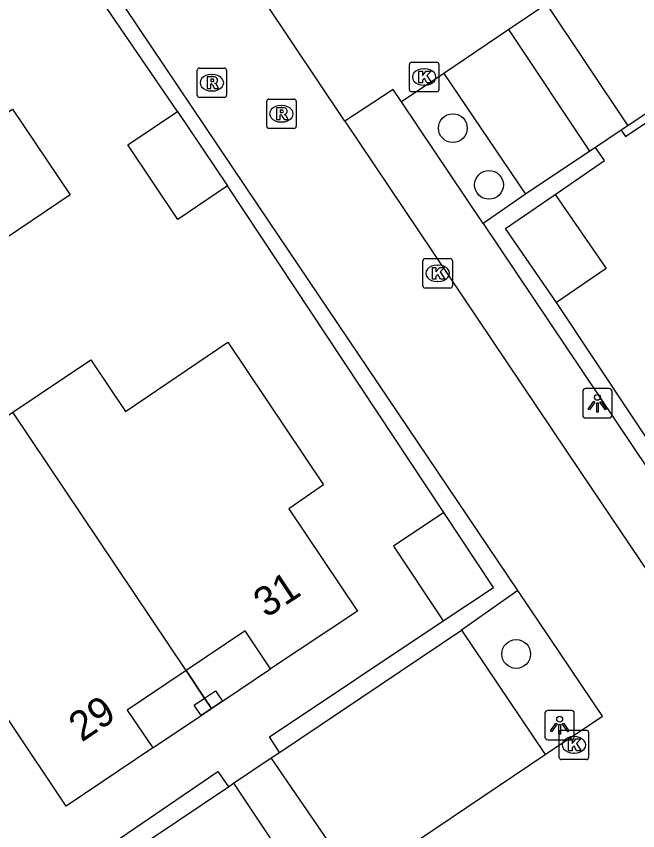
# Model space of a CAD drawing. Extents: x 158797 to 159887, y 384318 to 385255.
# Drawn here: x 158996.31 to 159017.41, y 384665 to 384692.68 of the extents above; entities that cross this region are included whole.
import ezdxf

# ---------------------------------------------------------------- set-up
doc = ezdxf.new("R2010")
doc.units = 0
for name, color, linetype in [('IMGEO_Boom', 7, 'Continuous'), ('IMGEO_Haag', 7, 'Continuous'), ('IMGEO_Kolk', 7, 'Continuous'), ('IMGEO_Lichtpunt', 7, 'Continuous'), ('IMGEO_Pand', 7, 'Continuous'), ('IMGEO_Pand_nummerreeks', 7, 'Continuous'), ('IMGEO_Pand_overbouw', 7, 'Continuous'), ('IMGEO_Parkeervlak_open', 7, 'Continuous'), ('IMGEO_Rijbaan_lokaal_open', 7, 'Continuous'), ('IMGEO_Rioolput', 7, 'Continuous'), ('IMGEO_Voetpad_open', 7, 'Continuous')]:
    doc.layers.add(name, color=color, linetype=linetype)

msp = doc.modelspace()

# ---------------------------------------------------------------- linework, layer by layer
at = {"layer": 'IMGEO_Boom'}
for centre in [(159011.135, 384688.876), (159012.361, 384686.948), (159013.286, 384671.004)]:
    msp.add_circle(centre, 0.489, dxfattribs=at)
at = {"layer": 'IMGEO_Haag'}
for points in [[(159016.845, 384688.805), (159016.999, 384688.587), (159030.87, 384697.932), (159024.718, 384707.573), (159022.492, 384711.051), (159035.359, 384719.573)], [(159001.782, 384689.447), (158999.092, 384693.395), (158999.536, 384693.676)], [(159014.609, 384686.625), (159016.285, 384687.777), (159015.976, 384688.222)], [(159010.822, 384675.811), (159003.482, 384686.92)], [(159013.604, 384686.631), (159012.161, 384685.634)], [(159022.309, 384671.435), (159014.649, 384682.946)], [(159013.342, 384673.159), (159011.423, 384671.817)], [(159005.247, 384667.662), (159004.91, 384668.192), (159010.81, 384672.13)], [(158997.48, 384663.137), (159003.151, 384667.014), (159003.509, 384666.492)]]:
    msp.add_lwpolyline(points, dxfattribs=at)
at = {"layer": 'IMGEO_Kolk'}
for p, q in [((159009.733, 384691.114), (159010.585, 384691.114)), ((159009.658, 384690.188), (159009.658, 384691.04)), ((159010.146, 384690.894), (159010.171, 384690.894)), ((159010.659, 384691.04), (159010.659, 384690.188)), ((159010.169, 384690.334), (159010.144, 384690.334)), ((159010.585, 384690.114), (159009.733, 384690.114)), ((159010.191, 384684.442), (159011.043, 384684.442)), ((159010.116, 384683.516), (159010.116, 384684.368)), ((159010.604, 384684.222), (159010.629, 384684.222)), ((159011.117, 384684.368), (159011.117, 384683.516)), ((159010.627, 384683.662), (159010.602, 384683.662)), ((159011.043, 384683.442), (159010.191, 384683.442)), ((159014.82, 384668.417), (159015.672, 384668.417)), ((159014.745, 384667.491), (159014.745, 384668.343)), ((159015.233, 384668.197), (159015.258, 384668.197)), ((159015.746, 384668.343), (159015.746, 384667.491)), ((159015.256, 384667.637), (159015.231, 384667.637)), ((159015.672, 384667.417), (159014.82, 384667.417))]:
    msp.add_line(p, q, dxfattribs=at)
for points in [[(159009.733, 384691.114), (159010.585, 384691.114)], [(159009.658, 384690.188), (159009.658, 384691.04)], [(159009.979, 384690.814), (159010.102, 384690.814), (159010.102, 384690.663), (159010.232, 384690.814), (159010.396, 384690.814), (159010.25, 384690.663), (159010.403, 384690.414), (159010.251, 384690.414), (159010.166, 384690.578), (159010.102, 384690.511), (159010.102, 384690.414), (159009.979, 384690.414), (159009.979, 384690.814)], [(159010.659, 384691.04), (159010.659, 384690.188)], [(159010.585, 384690.114), (159009.733, 384690.114)], [(159010.191, 384684.442), (159011.043, 384684.442)], [(159010.116, 384683.516), (159010.116, 384684.368)], [(159011.117, 384684.368), (159011.117, 384683.516)], [(159010.437, 384684.142), (159010.56, 384684.142), (159010.56, 384683.991), (159010.69, 384684.142), (159010.854, 384684.142), (159010.708, 384683.991), (159010.861, 384683.742), (159010.709, 384683.742), (159010.624, 384683.906), (159010.56, 384683.839), (159010.56, 384683.742), (159010.437, 384683.742), (159010.437, 384684.142)], [(159011.043, 384683.442), (159010.191, 384683.442)], [(159014.82, 384668.417), (159015.672, 384668.417)], [(159014.745, 384667.491), (159014.745, 384668.343)], [(159015.066, 384668.117), (159015.189, 384668.117), (159015.189, 384667.966), (159015.319, 384668.117), (159015.483, 384668.117), (159015.337, 384667.966), (159015.49, 384667.717), (159015.338, 384667.717), (159015.253, 384667.881), (159015.189, 384667.814), (159015.189, 384667.717), (159015.066, 384667.717), (159015.066, 384668.117)], [(159015.746, 384668.343), (159015.746, 384667.491)], [(159015.672, 384667.417), (159014.82, 384667.417)]]:
    msp.add_lwpolyline(points, dxfattribs=at)
for centre, start, end in [((159009.735, 384691.038), 91.552, 178.448), ((159009.735, 384691.038), 91.552, 178.448), ((159010.583, 384691.038), 1.552, 88.448), ((159010.583, 384691.038), 1.552, 88.448), ((159009.735, 384690.19), 181.552, 268.448), ((159009.735, 384690.19), 181.552, 268.448), ((159010.583, 384690.19), 271.552, 358.448), ((159010.583, 384690.19), 271.552, 358.448), ((159010.193, 384684.366), 91.552, 178.448), ((159010.193, 384684.366), 91.552, 178.448), ((159011.041, 384684.366), 1.552, 88.448), ((159011.041, 384684.366), 1.552, 88.448), ((159010.193, 384683.518), 181.552, 268.448), ((159010.193, 384683.518), 181.552, 268.448), ((159011.041, 384683.518), 271.552, 358.448), ((159011.041, 384683.518), 271.552, 358.448), ((159014.822, 384668.341), 91.552, 178.448), ((159014.822, 384668.341), 91.552, 178.448), ((159015.67, 384668.341), 1.552, 88.448), ((159015.67, 384668.341), 1.552, 88.448), ((159014.822, 384667.493), 181.552, 268.448), ((159014.822, 384667.493), 181.552, 268.448), ((159015.67, 384667.493), 271.552, 358.448), ((159015.67, 384667.493), 271.552, 358.448)]:
    msp.add_arc(centre, 0.0765, start, end, dxfattribs=at)
for centre, major_axis, ratio, start_param, end_param in [((159010.145, 384690.614), (-0.387, 0.002), 0.722429, 4.712389, 7.853982), ((159010.17, 384690.614), (-0.39, 0.002), 0.717154, 1.570796, 4.712389), ((159010.603, 384683.942), (-0.387, 0.002), 0.722429, 4.712389, 7.853982), ((159010.628, 384683.942), (-0.39, 0.002), 0.717154, 1.570796, 4.712389), ((159015.232, 384667.917), (-0.387, 0.002), 0.722429, 4.712389, 7.853982), ((159015.257, 384667.917), (-0.39, 0.002), 0.717154, 1.570796, 4.712389)]:
    msp.add_ellipse(centre, major_axis=major_axis, ratio=ratio, start_param=start_param, end_param=end_param, dxfattribs=at)
at = {"layer": 'IMGEO_Lichtpunt'}
for p, q in [((159016.447, 384680.024), (159015.639, 384680.024)), ((159016.447, 384680.024), (159015.639, 384680.024)), ((159015.545, 384679.929), (159015.545, 384679.122)), ((159015.545, 384679.929), (159015.545, 384679.122)), ((159016.541, 384679.122), (159016.541, 384679.929)), ((159016.541, 384679.122), (159016.541, 384679.929)), ((159015.639, 384679.028), (159016.447, 384679.028)), ((159015.639, 384679.028), (159016.447, 384679.028)), ((159014.263, 384668.991), (159014.263, 384668.184)), ((159014.263, 384668.991), (159014.263, 384668.184)), ((159015.165, 384669.086), (159014.357, 384669.086)), ((159015.165, 384669.086), (159014.357, 384669.086)), ((159015.259, 384668.184), (159015.259, 384668.991)), ((159015.259, 384668.184), (159015.259, 384668.991)), ((159014.357, 384668.09), (159015.165, 384668.09)), ((159014.357, 384668.09), (159015.165, 384668.09))]:
    msp.add_line(p, q, dxfattribs=at)
for points in [[(159015.919, 384679.593), (159015.958, 384679.565), (159015.77, 384679.303), (159015.732, 384679.33), (159015.919, 384679.593)], [(159016.021, 384679.545), (159016.068, 384679.545), (159016.068, 384679.223), (159016.021, 384679.223), (159016.021, 384679.545)], [(159016.131, 384679.565), (159016.169, 384679.592), (159016.356, 384679.33), (159016.317, 384679.302), (159016.131, 384679.565)], [(159014.637, 384668.655), (159014.676, 384668.627), (159014.488, 384668.365), (159014.45, 384668.392), (159014.637, 384668.655)], [(159014.739, 384668.607), (159014.786, 384668.607), (159014.786, 384668.285), (159014.739, 384668.285), (159014.739, 384668.607)], [(159014.849, 384668.627), (159014.887, 384668.654), (159015.074, 384668.392), (159015.035, 384668.364), (159014.849, 384668.627)]]:
    msp.add_lwpolyline(points, dxfattribs=at)
for centre in [(159016.044, 384679.727), (159014.762, 384668.789)]:
    msp.add_circle(centre, 0.0994, dxfattribs=at)
for centre, start, end in [((159015.639, 384679.929), 90, 180), ((159015.639, 384679.929), 90, 180), ((159016.447, 384679.929), 0, 90), ((159016.447, 384679.929), 0, 90), ((159015.639, 384679.122), 180, 270), ((159015.639, 384679.122), 180, 270), ((159016.447, 384679.122), 270, 0), ((159016.447, 384679.122), 270, 360), ((159014.357, 384668.991), 90, 180), ((159014.357, 384668.991), 90, 180), ((159015.165, 384668.991), 0, 90), ((159015.165, 384668.991), 0, 90), ((159014.357, 384668.184), 180, 270), ((159014.357, 384668.184), 180, 270), ((159015.165, 384668.184), 270, 0), ((159015.165, 384668.184), 270, 360)]:
    msp.add_arc(centre, 0.0946, start, end, dxfattribs=at)
at = {"layer": 'IMGEO_Pand'}
for points in [[(158993.552, 384690.663), (158994.895, 384688.659), (158996.173, 384689.52), (158998.134, 384686.609), (158994.667, 384684.273), (158995.465, 384683.072), (158990.615, 384679.83), (158988.303, 384683.292), (158986.558, 384682.126), (158984.781, 384684.772)], [(159003.482, 384686.92), (159001.792, 384685.777), (159000.089, 384688.308), (159001.782, 384689.447)], [(159001.782, 384689.447), (159003.482, 384686.92)], [(159014.649, 384682.946), (159012.919, 384685.463), (159014.609, 384686.625)], [(159014.609, 384686.625), (159016.337, 384684.111), (159014.649, 384682.946)], [(158996.189, 384679.224), (158998.841, 384681.001), (159000.016, 384679.247), (159003.486, 384681.6), (159006.744, 384676.751), (159005.562, 384675.944), (159007.89, 384672.465), (159004.941, 384670.502), (159004.077, 384671.792), (159002.074, 384670.439)], [(159002.074, 384670.439), (159000.077, 384669.091), (159000.945, 384667.812), (158998.004, 384665.834), (158992.405, 384674.193), (158994.691, 384675.724), (158993.536, 384677.447), (158996.189, 384679.224)], [(159002.074, 384670.439), (158996.189, 384679.224)], [(159010.822, 384675.811), (159009.119, 384674.672), (159010.81, 384672.13)], [(159010.81, 384672.13), (159012.516, 384673.264), (159010.822, 384675.811)], [(159002.936, 384669.153), (159002.587, 384668.918), (159002.35, 384669.271), (159002.699, 384669.506)], [(159002.699, 384669.506), (159003.072, 384669.756), (159003.309, 384669.404), (159002.936, 384669.153)], [(159002.936, 384669.153), (159002.699, 384669.506)]]:
    msp.add_lwpolyline(points, dxfattribs=at)
at = {"layer": 'IMGEO_Pand_overbouw'}
for points in [[(159002.074, 384670.439), (159002.699, 384669.506), (159002.936, 384669.153), (159003.309, 384669.404), (159004.941, 384670.502), (159004.077, 384671.792)], [(159002.587, 384668.918), (159002.936, 384669.153), (159002.699, 384669.506), (159002.074, 384670.439), (159000.077, 384669.091), (159000.945, 384667.812)]]:
    msp.add_lwpolyline(points, close=True, dxfattribs=at)
at = {"layer": 'IMGEO_Parkeervlak_open'}
for points in [[(159027.614, 384696.029), (159017.072, 384688.957)], [(159010.828, 384690.734), (159013.604, 384686.631)], [(159015.785, 384688.094), (159013.604, 384686.631)], [(159005.247, 384667.662), (159011.423, 384671.817)], [(159011.423, 384671.817), (159014.269, 384667.587)], [(159004.967, 384667.473), (159005.247, 384667.662)], [(158997.323, 384662.331), (159003.509, 384666.492)], [(159003.509, 384666.492), (159003.688, 384666.613)]]:
    msp.add_lwpolyline(points, dxfattribs=at)
at = {"layer": 'IMGEO_Rijbaan_lokaal_open'}
for points in [[(159013.342, 384673.159), (159004.533, 384686.241), (158999.536, 384693.676)], [(159007.469, 384689.118), (159004.736, 384693.195)], [(159014.319, 384693.094), (159013.039, 384692.228)], [(159013.039, 384692.228), (159010.828, 384690.734)], [(159010.828, 384690.734), (159009.384, 384689.772)], [(159007.469, 384689.118), (159015.48, 384677.168), (159023.424, 384665.376), (159040.186, 384676.652), (159060.67, 384690.454)], [(159009.384, 384689.772), (159009.103, 384690.19), (159007.469, 384689.118)], [(159014.269, 384667.587), (159016.213, 384668.895), (159013.342, 384673.159)], [(159007.845, 384663.262), (159014.269, 384667.587)]]:
    msp.add_lwpolyline(points, dxfattribs=at)
at = {"layer": 'IMGEO_Rioolput'}
for p, q in [((159002.448, 384689.993), (159002.448, 384690.845)), ((159002.523, 384690.919), (159003.375, 384690.919)), ((159003.449, 384690.845), (159003.449, 384689.993)), ((159002.936, 384690.699), (159002.961, 384690.699)), ((159002.959, 384690.139), (159002.934, 384690.139)), ((159003.375, 384689.919), (159002.523, 384689.919)), ((159004.811, 384688.939), (159004.811, 384689.791)), ((159004.886, 384689.865), (159005.738, 384689.865)), ((159005.812, 384689.791), (159005.812, 384688.939)), ((159005.299, 384689.645), (159005.324, 384689.645)), ((159005.738, 384688.865), (159004.886, 384688.865)), ((159005.322, 384689.085), (159005.297, 384689.085))]:
    msp.add_line(p, q, dxfattribs=at)
for points in [[(159002.448, 384689.993), (159002.448, 384690.845)], [(159002.523, 384690.919), (159003.375, 384690.919)], [(159003.449, 384690.845), (159003.449, 384689.993)], [(159003.037, 384690.617), (159002.785, 384690.619), (159002.785, 384690.219)], [(159002.963, 384690.538), (159002.909, 384690.538), (159002.909, 384690.457)], [(159002.785, 384690.219), (159002.909, 384690.219), (159002.909, 384690.381), (159002.92, 384690.381)], [(159002.909, 384690.457), (159002.961, 384690.457)], [(159002.967, 384690.352), (159003.038, 384690.219), (159003.178, 384690.219), (159003.113, 384690.345)], [(159003.375, 384689.919), (159002.523, 384689.919)], [(159004.811, 384688.939), (159004.811, 384689.791)], [(159004.886, 384689.865), (159005.738, 384689.865)], [(159005.812, 384689.791), (159005.812, 384688.939)], [(159005.4, 384689.563), (159005.148, 384689.565), (159005.148, 384689.165)], [(159005.326, 384689.484), (159005.272, 384689.484), (159005.272, 384689.403)], [(159005.148, 384689.165), (159005.272, 384689.165), (159005.272, 384689.327), (159005.283, 384689.327)], [(159005.272, 384689.403), (159005.324, 384689.403)], [(159005.33, 384689.298), (159005.401, 384689.165), (159005.541, 384689.165), (159005.476, 384689.291)], [(159005.738, 384688.865), (159004.886, 384688.865)]]:
    msp.add_lwpolyline(points, dxfattribs=at)
for centre, radius, start, end in [((159002.525, 384690.843), 0.0765, 91.552, 178.448), ((159002.525, 384690.843), 0.0765, 91.552, 178.448), ((159003.373, 384690.843), 0.0765, 1.552, 88.448), ((159003.373, 384690.843), 0.0765, 1.552, 88.448), ((159002.969, 384690.442), 0.0964, 77.0061, 93.1865), ((159002.983, 384690.499), 0.0378, 276.6634, 79.6772), ((159003.036, 384690.507), 0.109, 350.3612, 89.416), ((159002.919, 384690.328), 0.0533, 26.0293, 88.6989), ((159002.945, 384690.646), 0.19, 274.7715, 282.9687), ((159003.034, 384690.507), 0.112, 277.5842, 350.9817), ((159003.018, 384690.292), 0.108, 29.5134, 73.7905), ((159002.525, 384689.995), 0.0765, 181.552, 268.448), ((159002.525, 384689.995), 0.0765, 181.552, 268.448), ((159003.373, 384689.995), 0.0765, 271.552, 358.448), ((159003.373, 384689.995), 0.0765, 271.552, 358.448), ((159004.888, 384689.789), 0.0765, 91.552, 178.448), ((159004.888, 384689.789), 0.0765, 91.552, 178.448), ((159005.736, 384689.789), 0.0765, 1.552, 88.448), ((159005.736, 384689.789), 0.0765, 1.552, 88.448), ((159005.332, 384689.388), 0.0964, 77.0061, 93.1865), ((159005.346, 384689.445), 0.0378, 276.6634, 79.6772), ((159005.399, 384689.453), 0.109, 350.3612, 89.416), ((159005.397, 384689.453), 0.112, 277.5842, 350.9817), ((159005.282, 384689.274), 0.0533, 26.0293, 88.6989), ((159005.308, 384689.592), 0.19, 274.7715, 282.9687), ((159005.381, 384689.238), 0.108, 29.5134, 73.7905), ((159004.888, 384688.941), 0.0765, 181.552, 268.448), ((159004.888, 384688.941), 0.0765, 181.552, 268.448), ((159005.736, 384688.941), 0.0765, 271.552, 358.448), ((159005.736, 384688.941), 0.0765, 271.552, 358.448)]:
    msp.add_arc(centre, radius, start, end, dxfattribs=at)
for centre, major_axis, ratio, start_param, end_param in [((159002.935, 384690.419), (-0.387, 0.002), 0.722429, 4.712389, 7.853982), ((159002.96, 384690.419), (-0.39, 0.002), 0.717154, 1.570796, 4.712389), ((159005.298, 384689.365), (-0.387, 0.002), 0.722429, 4.712389, 7.853982), ((159005.323, 384689.365), (-0.39, 0.002), 0.717154, 1.570796, 4.712389)]:
    msp.add_ellipse(centre, major_axis=major_axis, ratio=ratio, start_param=start_param, end_param=end_param, dxfattribs=at)
at = {"layer": 'IMGEO_Voetpad_open'}
for points in [[(159014.319, 384693.094), (159017.072, 384688.957)], [(159015.785, 384688.094), (159013.039, 384692.228)], [(159012.161, 384685.634), (159009.384, 384689.772)], [(159017.072, 384688.957), (159016.845, 384688.805)], [(159016.845, 384688.805), (159015.976, 384688.222)], [(159015.976, 384688.222), (159015.785, 384688.094)], [(159012.161, 384685.634), (159023.393, 384668.892), (159023.532, 384668.866)], [(159003.688, 384666.613), (159004.967, 384667.473)], [(159007.845, 384663.262), (159004.967, 384667.473)], [(159003.688, 384666.613), (159006.515, 384662.367)]]:
    msp.add_lwpolyline(points, dxfattribs=at)

# ---------------------------------------------------------------- texts
at = {"layer": 'IMGEO_Pand_nummerreeks'}
for s, rotation, p in [('31', 33.6498, (159004.798, 384672.209)), ('29', 33.9248, (158998.527, 384667.993))]:
    msp.add_text(s, height=1, rotation=rotation, dxfattribs=at).set_placement(p)

doc.saveas('drawing.dxf')
